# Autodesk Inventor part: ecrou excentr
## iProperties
Created: 2009-10
Part Number: ecrou excentr
Document SubType Name: Modeling
Designer: Olivier
Density: 1 g/cm^3
Author: Olivier
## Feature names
1. Extrusion1
2. Révolution1 [Revolution]
3. Extrusion3
